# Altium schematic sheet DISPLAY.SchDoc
size A3
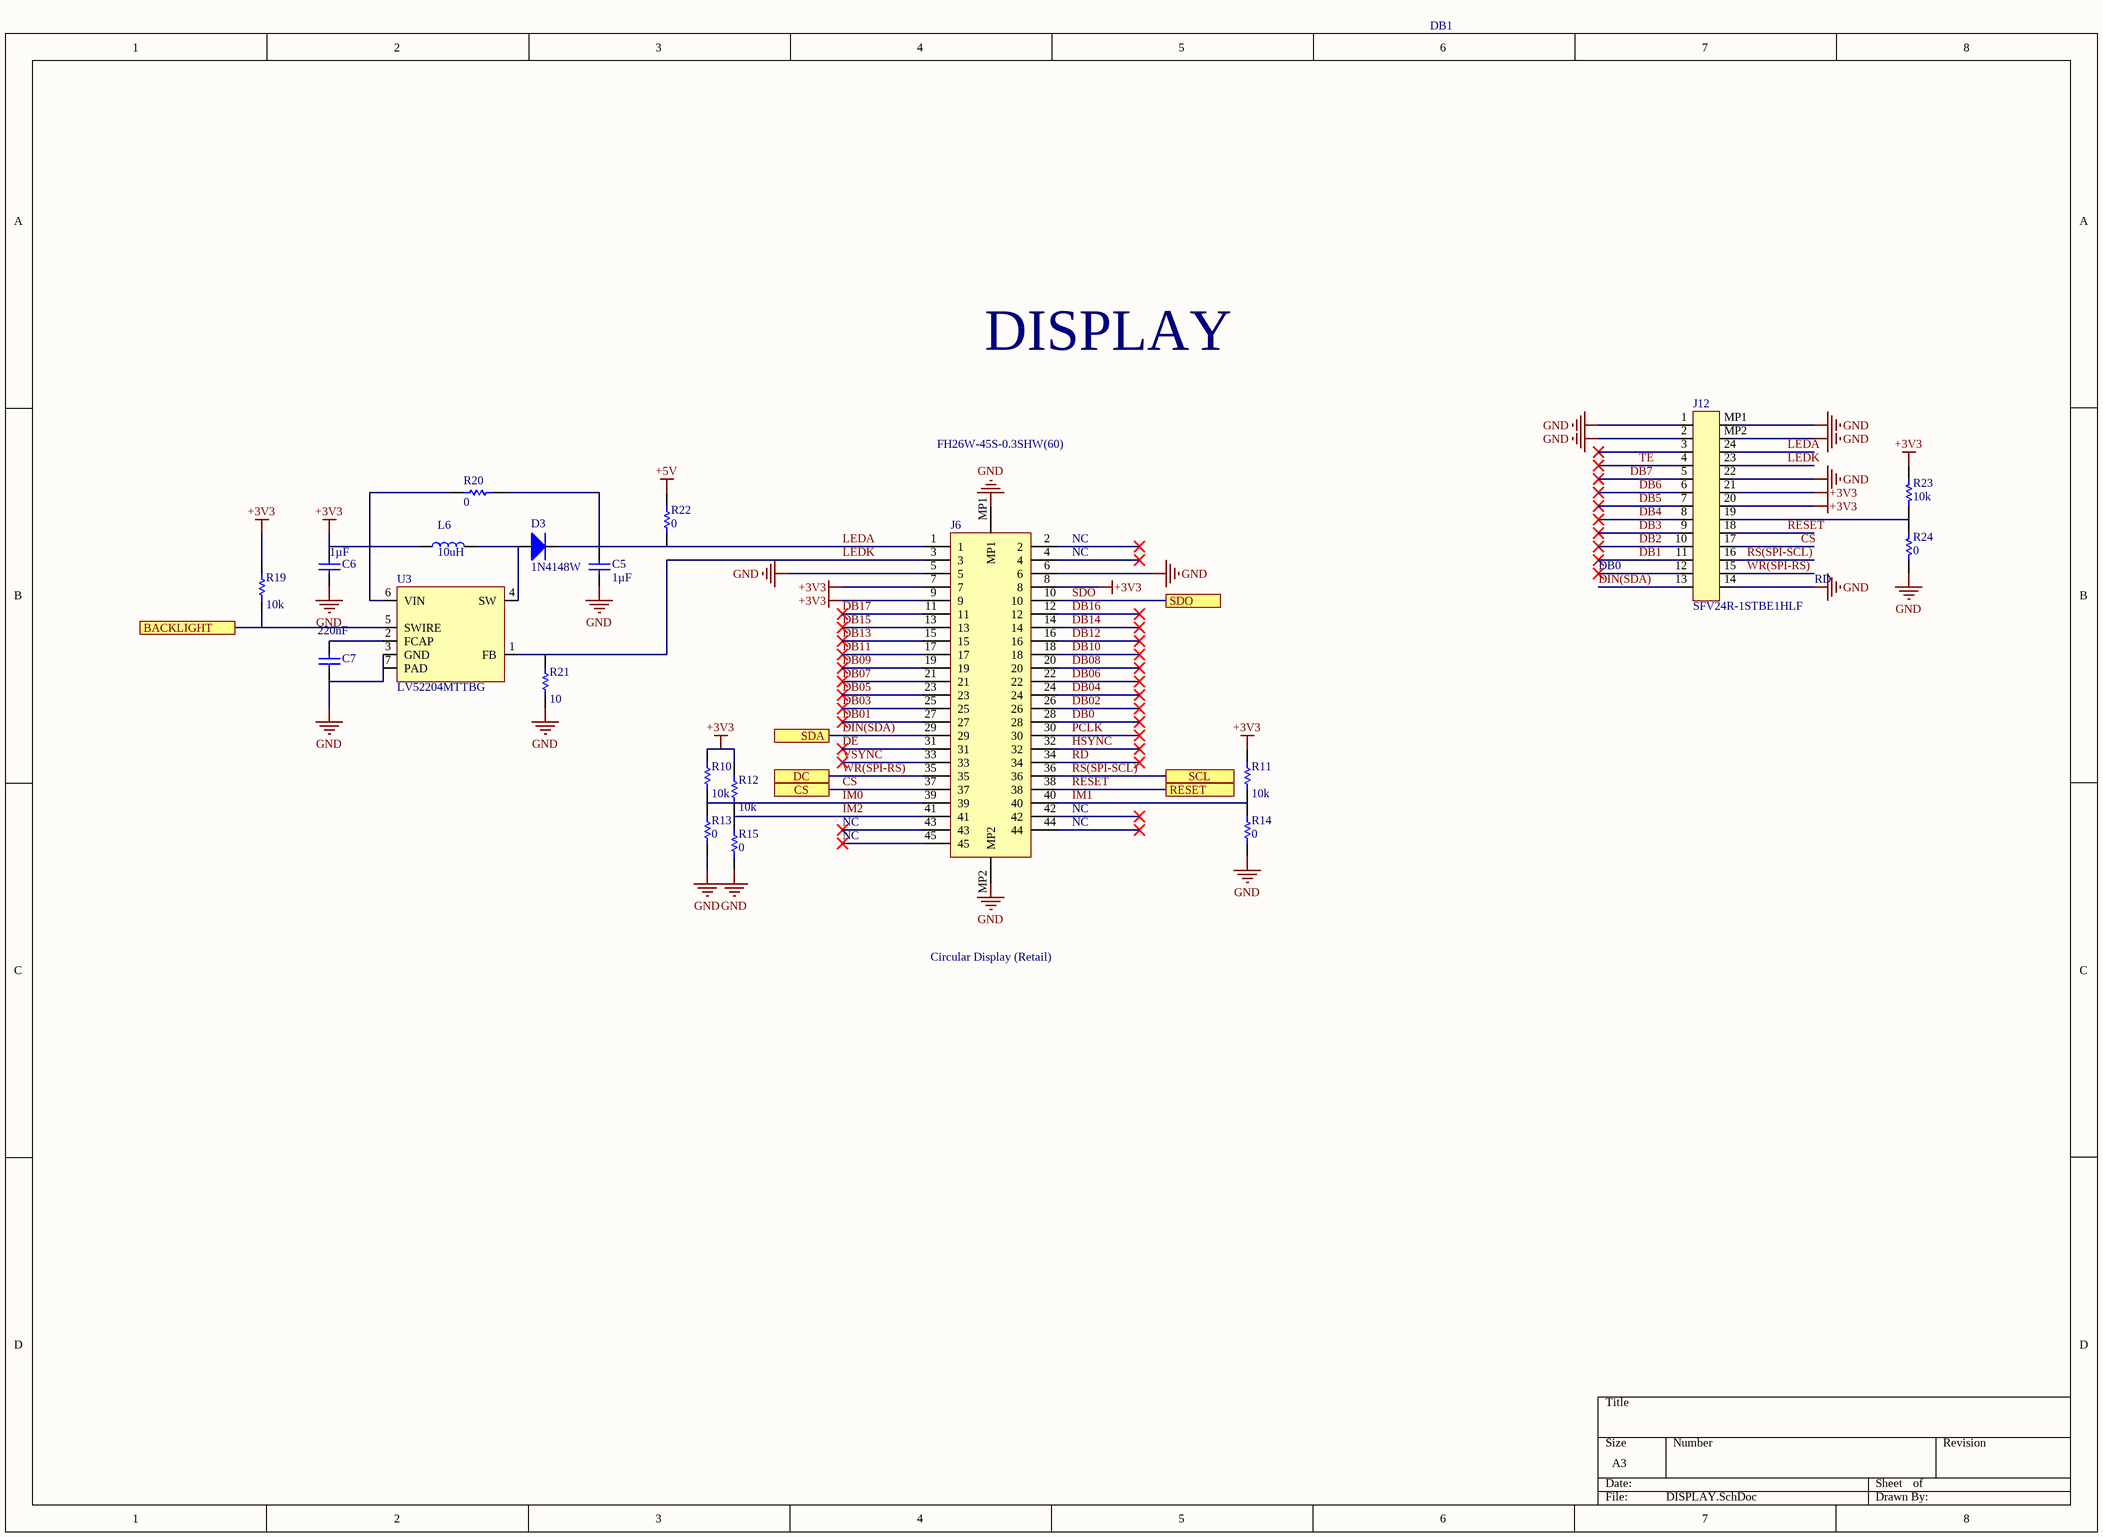
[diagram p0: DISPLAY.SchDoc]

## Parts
C5  value 1µF  [CAP-0805]  (hidden comment: GCM21BC72A105KE36L)
C6  value 1µF  [CAP-0402]  (hidden comment: C0402C105M9PACTU)
C7  value 220nF  [CAP-0402]  (hidden comment: C0402C224K9PACTU)
D3  1N4148W  [SOD123-1]
J6  FH26W-45S-0.3SHW(60)  [FH26W-45S-0.3SHW(60)-Footprint-1]
J12  SFV24R-1STBE1HLF  [SFV24R-1STBE1HLF-Footprint-1]
L6  SRR0604-100ML  [SRR0604-100ML-Footprint-1]  (value not drawn)
R10  value 10k  [RES-0402]  (hidden comment: CRCW040210K0JNED)
R11  value 10k  [RES-0402]  (hidden comment: CRCW040210K0JNED)
R12  value 10k  [RES-0402]  (hidden comment: CRCW040210K0JNED)
R13  value 0  [RES-0402]  (hidden comment: CRCW04020000Z0EDC)
R14  value 0  [RES-0402]  (hidden comment: CRCW04020000Z0EDC)
R15  value 0  [RES-0402]  (hidden comment: CRCW04020000Z0EDC)
R19  value 10k  [RES-0402]  (hidden comment: CRCW040210K0JNED)
R20  value 0  [RES-0402]  (hidden comment: CRCW04020000Z0EDC)
R21  value 10  [RES-0402]  (hidden comment: RC0402FR-0710RL)
R22  value 0  [RES-0402]  (hidden comment: CRCW04020000Z0EDC)
R23  value 10k  [RES-0402]  (hidden comment: CRCW040210K0JNED)
R24  value 0  [RES-0402]  (hidden comment: CRCW04020000Z0EDC)
U3  LV52204MTTBG  [QFN65P200X200X80_HS-7L]

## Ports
BACKLIGHT, CS, DC, RESET, SCL, SDA, SDO

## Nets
+3V3: C6.2 J6.7 J6.8 J6.9 J12.20 J12.21 L6.1 R10.2 R11.2 R12.2 R19.2 R20.2 R23.2 U3.6(VIN)
+5V: R22.1
GND: C5.1 C6.1 C7.1 J6.5 J6.6 J6.MP1 J6.MP2 J12.1 J12.2 J12.14 J12.22 J12.MP1 J12.MP2 R13.1 R14.1 R15.1 R21.1 R24.1 U3.3(GND) U3.7(PAD)
BACKLIGHT: R19.1 U3.5(SWIRE) ; port BACKLIGHT
CS: J6.37 J12.17 ; port CS
DB0: J6.28
DB01: J6.27
DB1: J12.11
DB02: J6.26
DB2: J12.10
DB03: J6.25
DB3: J12.9
DB04: J6.24
DB4: J12.8
DB05: J6.23
DB5: J12.7
DB06: J6.22
DB6: J12.6
DB07: J6.21
DB7: J12.5
DB08: J6.20
DB09: J6.19
DB10: J6.18
DB11: J6.17
DB12: J6.16
DB13: J6.15
DB14: J6.14
DB15: J6.13
DB16: J6.12
DB17: J6.11
DE: J6.31
DIN(SDA): J6.29 J12.13 ; port SDA
HSYNC: J6.32
IM0: J6.39 R10.1 R13.2
IM1: J6.40 R11.1 R14.2
IM2: J6.41 R12.1 R15.2
LEDA: C5.2 D3.C J6.1 J12.24 R20.1 R22.2
LEDK: J6.3 J12.23 R21.2 U3.1(FB)
PCLK: J6.30
RD: J6.34
RESET: J6.38 J12.18 ; port RESET
RS(SPI-SCL): J6.36 J12.16 ; port SCL
SDO: J6.10 ; port SDO
TE: J12.4
VSYNC: J6.33
WR(SPI-RS): J6.35 J12.15 ; port DC
NetC7_2: C7.2 U3.2(FCAP)
NetD3_A: D3.A L6.2 U3.4(SW)
NetJ12_19: J12.19 R23.1 R24.2

Not connected (* = marked no-connect by the designer): J6 2* 4* 42* 43* 44* 45*; J12 3* 12*

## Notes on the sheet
- DB1
- DISPLAY
- (near J6) NC
- (near L6) 10uH
- DB0
- RD
- NC
- Circular Display (Retail)

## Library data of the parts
C5 = C0084-A.1: CAP CHIP 0805 1uF 100V X7S 10%; Manufacturer: Murata; Code Arduino: C0084
C6 = C0019-A.3: CAP CHIP 0402 1uF 6V3 X5R 20%; Manufacturer: KEMET; Code Arduino: 0133; Voltage: 6.3V
C7 = C0088-A.2: CAP CHIP 0402 220nF 6.3V X5R 10%; Manufacturer: KEMET; Dissipation Factor: 5%; Code Arduino: C0088; Dielectric Material: Ceramic
D3 = D0029-A.2: DIODE FAST SMD 200mA 100V SOD123; Manufacturer: Vishay; Code Arduino: 0290; Device Type: Diode gen. Purp
J6 = J0028-A.2: CONN FPC/FFC 41POS .3MM; Manufacturer: Hirose; Pitch: 0.012inch; Current Rating: 200mA; Voltage Rating: 30V; Number of Positions: 45; Actuator Material: Nylon,Polyamide; Code Arduino: J0028
J12 = J0102-A.1: CONN FPC SMD SKT 24 POS 0.5mm RA SMD; Manufacturer: Amphenol FCI; Current Rating: 500mA; Code Arduino: J0102; Voltage Rating: 50V; Wire/Cable Type: Straight; Actuator Material: Glass,Polyphenylene; Insulation Resistance: 100MR; Number of Contacts: 24; Contact Resistance: 30mR; Contact Location: Bottom
L6 = I0013-A.2: FIXED IND 10UH 1.3A 120 MOHM SMD; Manufacturer: Bourns; Frequency: 30MHz; Tolerance: 20%; DC Resistance (DCR): 120mR; Test Frequency: 2.52MHz; Code Arduino: 0031
R10-R12 R19 R23 = R0004-A.3: RES CHIP 0402 10K 5% 1/16W; Manufacturer: Vishay; Code Arduino: 0136; Power: 63mW
R13-R15 R20 R22 R24 = R0000-A.3: RES CHIP 0402 0R 1/16W; Manufacturer: Vishay; Code Arduino: 0039; Power: 63mW; Tolerance: J
R21 = R0170-A.1: RES CHIP 0402 10 OHM 1/16W 1%; Manufacturer: Yageo; Power: 63mW; Working Voltage: 50V; Temperature Coefficient: 100ppm/°C; Resistance: 10R; Code Arduino: R0170
U3 = U0125-A.6: IC LED BOOST DRIVER; Manufacturer: ON Semiconductor; Number of Outputs: 1; Output Current per Channel: 700mA; Max Supply Voltage: 5.5V; Switching Frequency: 600kHz; Nominal Input Voltage (DC): 3.6V; Code Arduino: U0125; Dimming: PWM,Single-Wire; Max Output Voltage: 39V; Min Input Voltage: 2.7V; Min Output Voltage: 37V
